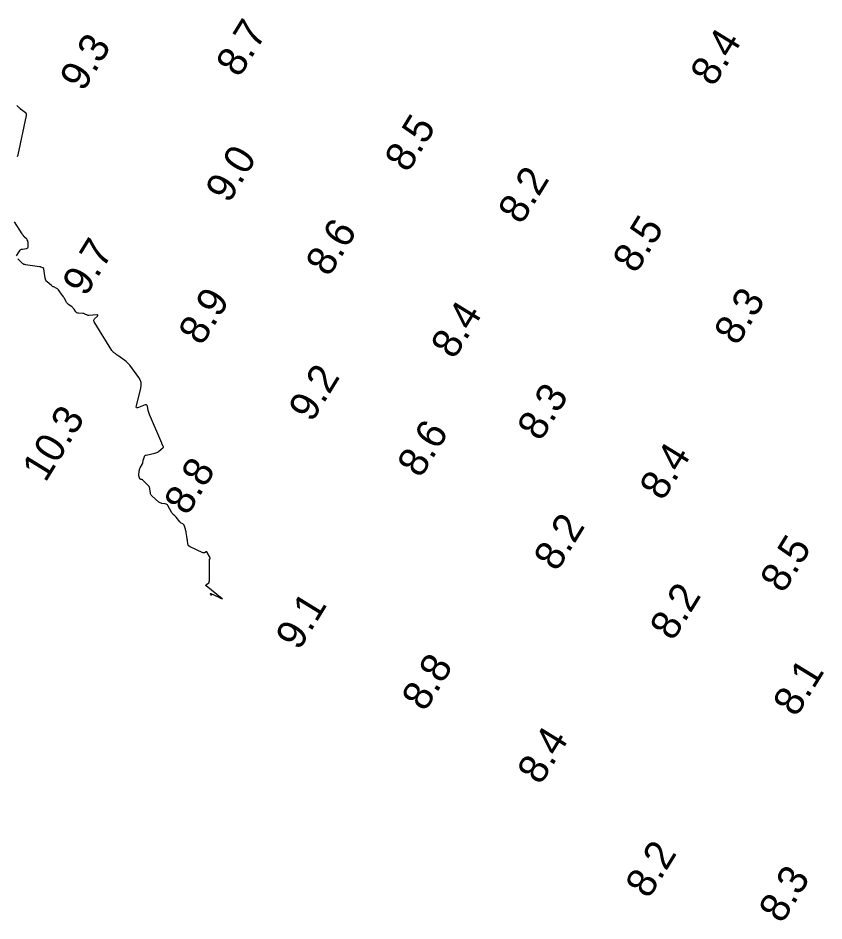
# Model space of a CAD drawing. Extents: x 1023796 to 1112670, y 656573 to 837340.
# Drawn here: x 1100873.9 to 1101010.5, y 687548 to 687701.1 of the extents above; entities that cross this region are included whole.
import ezdxf

# ---------------------------------------------------------------- set-up
doc = ezdxf.new("R2010")
doc.units = 0
doc.layers.add('V-CHAN-CONT-10FT', color=7, linetype='Continuous')
doc.layers.add('V-TOPO-SOUN', color=7, linetype='Continuous')

msp = doc.modelspace()

# ---------------------------------------------------------------- linework, layer by layer
at = {"layer": 'V-CHAN-CONT-10FT'}
for points in [[(1100873.86, 687677.67), (1100873.95, 687677.94), (1100875.39, 687684.58), (1100875.4, 687684.73), (1100875.38, 687684.86), (1100875.31, 687684.98), (1100875.2, 687685.08), (1100874.5, 687685.59), (1100874.46, 687685.62), (1100874.41, 687685.65), (1100874.37, 687685.69), (1100874.33, 687685.72), (1100874.17, 687685.87), (1100874.13, 687685.91), (1100874.09, 687685.95), (1100874.05, 687685.99), (1100874.02, 687686.03), (1100873.73, 687686.33)], [(1100873.65, 687660.79), (1100874.18, 687661.63), (1100874.28, 687661.76), (1100874.4, 687661.86), (1100874.53, 687661.93), (1100874.69, 687661.97), (1100875.38, 687662.08), (1100875.51, 687662.12), (1100875.61, 687662.19), (1100875.66, 687662.3), (1100875.67, 687662.44), (1100875.64, 687663.09), (1100875.62, 687663.24), (1100875.58, 687663.37), (1100875.51, 687663.5), (1100875.42, 687663.62), (1100875, 687664.06), (1100874.9, 687664.17), (1100874.8, 687664.29), (1100874.71, 687664.41), (1100874.63, 687664.53), (1100873.35, 687666.58)], [(1100906.76, 687603.23), (1100906.56, 687603.5), (1100906.53, 687603.54), (1100906.53, 687603.56), (1100906.55, 687603.56), (1100906.59, 687603.55), (1100907.95, 687602.93), (1100908.03, 687602.9), (1100908.1, 687602.86), (1100908.17, 687602.83), (1100908.25, 687602.79), (1100908.54, 687602.64), (1100908.59, 687602.61), (1100908.61, 687602.61), (1100908.6, 687602.63), (1100908.55, 687602.67), (1100905.85, 687604.86), (1100905.79, 687604.91), (1100905.78, 687604.97), (1100905.8, 687605.02), (1100905.86, 687605.07), (1100906.27, 687605.35), (1100906.29, 687605.36), (1100906.3, 687605.37), (1100906.31, 687605.39), (1100906.31, 687605.41), (1100906.34, 687605.48), (1100906.34, 687605.49), (1100906.35, 687605.51), (1100906.35, 687605.53), (1100906.35, 687605.54), (1100906.36, 687605.61), (1100906.36, 687605.63), (1100906.36, 687605.65), (1100906.37, 687605.66), (1100906.37, 687605.68), (1100906.39, 687609.4), (1100906.39, 687609.41), (1100906.4, 687609.43), (1100906.41, 687609.43), (1100906.42, 687609.44), (1100906.49, 687609.46), (1100906.51, 687609.46), (1100906.52, 687609.47), (1100906.52, 687609.48), (1100906.52, 687609.5), (1100906.45, 687609.69), (1100906.43, 687609.73), (1100906.42, 687609.77), (1100906.4, 687609.81), (1100906.38, 687609.84), (1100906.01, 687610.54), (1100905.98, 687610.59), (1100905.93, 687610.62), (1100905.87, 687610.62), (1100905.81, 687610.61), (1100905.55, 687610.48), (1100905.48, 687610.46), (1100905.41, 687610.45), (1100905.35, 687610.46), (1100905.28, 687610.48), (1100903.09, 687611.49), (1100902.95, 687611.57), (1100902.85, 687611.67), (1100902.78, 687611.8), (1100902.74, 687611.95), (1100902.64, 687612.6), (1100902.62, 687612.76), (1100902.6, 687612.92), (1100902.57, 687613.08), (1100902.55, 687613.23), (1100902.44, 687613.88), (1100902.41, 687614.03), (1100902.38, 687614.17), (1100902.34, 687614.31), (1100902.3, 687614.45), (1100902.08, 687615.14), (1100902.05, 687615.21), (1100902, 687615.27), (1100901.95, 687615.32), (1100901.88, 687615.36), (1100901.59, 687615.5), (1100901.52, 687615.53), (1100901.46, 687615.58), (1100901.4, 687615.63), (1100901.35, 687615.69), (1100900.74, 687616.48), (1100900.69, 687616.55), (1100900.63, 687616.62), (1100900.56, 687616.68), (1100900.5, 687616.74), (1100900.22, 687616.97), (1100900.16, 687617.03), (1100900.1, 687617.1), (1100900.04, 687617.17), (1100900, 687617.24), (1100899.33, 687618.47), (1100899.25, 687618.58), (1100899.16, 687618.67), (1100899.04, 687618.73), (1100898.9, 687618.76), (1100898.33, 687618.83), (1100898.19, 687618.86), (1100898.05, 687618.91), (1100897.93, 687618.98), (1100897.82, 687619.06), (1100896.64, 687620.11), (1100896.53, 687620.22), (1100896.45, 687620.35), (1100896.4, 687620.48), (1100896.37, 687620.64), (1100896.3, 687621.27), (1100896.28, 687621.42), (1100896.22, 687621.56), (1100896.15, 687621.69), (1100896.05, 687621.81), (1100895.11, 687622.8), (1100895.07, 687622.83), (1100895.03, 687622.85), (1100894.99, 687622.87), (1100894.94, 687622.88), (1100894.74, 687622.9), (1100894.7, 687622.92), (1100894.66, 687622.94), (1100894.63, 687622.97), (1100894.61, 687623.01), (1100894.48, 687623.33), (1100894.46, 687623.4), (1100894.44, 687623.47), (1100894.44, 687623.54), (1100894.44, 687623.62), (1100894.48, 687624.33), (1100894.5, 687624.47), (1100894.53, 687624.6), (1100894.58, 687624.74), (1100894.64, 687624.86), (1100895.03, 687625.53), (1100895.06, 687625.59), (1100895.08, 687625.65), (1100895.1, 687625.71), (1100895.11, 687625.78), (1100895.13, 687626.05), (1100895.14, 687626.12), (1100895.15, 687626.18), (1100895.17, 687626.25), (1100895.19, 687626.31), (1100895.36, 687626.78), (1100895.4, 687626.87), (1100895.46, 687626.94), (1100895.54, 687626.99), (1100895.63, 687627.02), (1100897.14, 687627.35), (1100897.31, 687627.4), (1100897.47, 687627.46), (1100897.63, 687627.55), (1100897.77, 687627.66), (1100898.5, 687628.26), (1100898.55, 687628.31), (1100898.57, 687628.36), (1100898.57, 687628.42), (1100898.55, 687628.49), (1100898.42, 687628.76), (1100898.39, 687628.83), (1100898.36, 687628.9), (1100898.33, 687628.96), (1100898.3, 687629.03), (1100896.21, 687633.91), (1100896.14, 687634.07), (1100896.08, 687634.25), (1100896.04, 687634.42), (1100896, 687634.59), (1100895.86, 687635.31), (1100895.81, 687635.45), (1100895.73, 687635.54), (1100895.61, 687635.56), (1100895.46, 687635.53), (1100894.36, 687635.08), (1100894.16, 687635.02), (1100894.03, 687635.06), (1100893.98, 687635.18), (1100894.01, 687635.38), (1100894.75, 687638.37), (1100894.82, 687638.86), (1100894.79, 687639.33), (1100894.64, 687639.78), (1100894.39, 687640.21), (1100892.87, 687642.25), (1100892.69, 687642.47), (1100892.5, 687642.68), (1100892.29, 687642.87), (1100892.06, 687643.04), (1100890.84, 687643.9), (1100890.75, 687643.96), (1100890.66, 687644.03), (1100890.58, 687644.1), (1100890.49, 687644.17), (1100890.14, 687644.44), (1100890.05, 687644.52), (1100889.98, 687644.6), (1100889.91, 687644.68), (1100889.85, 687644.77), (1100886.86, 687649.61), (1100886.79, 687649.75), (1100886.78, 687649.88), (1100886.83, 687650.01), (1100886.92, 687650.13), (1100887.39, 687650.59), (1100887.48, 687650.69), (1100887.49, 687650.75), (1100887.43, 687650.79), (1100887.3, 687650.8), (1100885.91, 687650.72), (1100885.83, 687650.72), (1100885.74, 687650.73), (1100885.66, 687650.76), (1100885.58, 687650.79), (1100885.26, 687650.95), (1100885.18, 687650.98), (1100885.1, 687651.01), (1100885.02, 687651.03), (1100884.93, 687651.03), (1100884.18, 687651.07), (1100884.05, 687651.09), (1100883.93, 687651.14), (1100883.83, 687651.21), (1100883.74, 687651.31), (1100883.43, 687651.78), (1100883.34, 687651.89), (1100883.25, 687652), (1100883.15, 687652.09), (1100883.04, 687652.18), (1100882.51, 687652.57), (1100882.39, 687652.67), (1100882.28, 687652.78), (1100882.18, 687652.9), (1100882.1, 687653.03), (1100881.79, 687653.61), (1100881.71, 687653.75), (1100881.63, 687653.89), (1100881.54, 687654.03), (1100881.44, 687654.16), (1100880.78, 687655.05), (1100880.7, 687655.14), (1100880.62, 687655.22), (1100880.52, 687655.28), (1100880.42, 687655.33), (1100879.99, 687655.53), (1100879.89, 687655.58), (1100879.79, 687655.64), (1100879.69, 687655.7), (1100879.6, 687655.78), (1100878.89, 687656.4), (1100878.76, 687656.53), (1100878.66, 687656.69), (1100878.58, 687656.86), (1100878.54, 687657.04), (1100878.3, 687658.59), (1100878.28, 687658.66), (1100878.25, 687658.71), (1100878.2, 687658.76), (1100878.14, 687658.79), (1100877.86, 687658.9), (1100877.79, 687658.92), (1100877.72, 687658.94), (1100877.65, 687658.96), (1100877.58, 687658.97), (1100875.22, 687659.29), (1100875.07, 687659.32), (1100874.94, 687659.37), (1100874.81, 687659.45), (1100874.7, 687659.54), (1100874.15, 687660.08), (1100874.09, 687660.14), (1100874.03, 687660.19), (1100873.98, 687660.25), (1100873.92, 687660.31)]]:
    msp.add_lwpolyline(points, dxfattribs=at)

# ---------------------------------------------------------------- texts
at = {"layer": 'V-TOPO-SOUN'}
for s, p in [('8.7', (1100911.45, 687690.88)), ('9.3', (1100884.97, 687688.49)), ('8.4', (1100991.83, 687689.31)), ('8.5', (1100940.02, 687674.76)), ('9.0', (1100909.66, 687669.55)), ('8.2', (1100959.25, 687665.95)), ('8.6', (1100926.64, 687657.09)), ('8.5', (1100978.67, 687657.64)), ('9.7', (1100885.4, 687653.74)), ('8.9', (1100905.08, 687645.41)), ('8.3', (1100995.86, 687645.41)), ('8.4', (1100947.86, 687643.11)), ('9.2', (1100923.75, 687632.42)), ('8.3', (1100962.5, 687629.2)), ('10.3 ', (1100878.58, 687622.25)), ('8.6', (1100942.16, 687622.97)), ('8.4', (1100983.23, 687619.1)), ('8.8', (1100902.65, 687616.6)), ('8.2', (1100965.29, 687607.12)), ('8.5', (1101003.67, 687603.44)), ('8.2', (1100984.97, 687595.34)), ('9.1', (1100921.55, 687593.74)), ('8.8', (1100942.91, 687583.37)), ('8.1', (1101005.84, 687582.46)), ('8.4', (1100962.5, 687570.94)), ('8.2', (1100980.84, 687551.64)), ('8.3', (1101003.44, 687547.44))]:
    msp.add_text(s, height=5, rotation=58.4285, dxfattribs=at).set_placement(p)

doc.saveas('drawing.dxf')
